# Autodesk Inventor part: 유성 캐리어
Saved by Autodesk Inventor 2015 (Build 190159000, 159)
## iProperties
Created: 2026-05
Part Number: 유성 캐리어
Material: 일반
Document SubType Name: Modeling
Designer: 104
Density: 1 g/cm^3
Appearance: 기본값
Author: 104
Author: jhkim
Creation Date: 2026-05-18
Sending System: Autodesk Inventor 2027
Preprocessor: ST-DEVELOPER v20.1
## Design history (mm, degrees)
node "유성 캐리어1"
node "솔리드1"
node "기준1"
